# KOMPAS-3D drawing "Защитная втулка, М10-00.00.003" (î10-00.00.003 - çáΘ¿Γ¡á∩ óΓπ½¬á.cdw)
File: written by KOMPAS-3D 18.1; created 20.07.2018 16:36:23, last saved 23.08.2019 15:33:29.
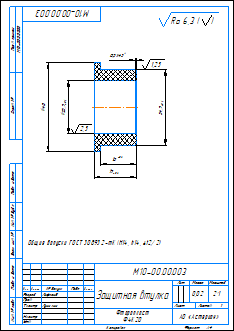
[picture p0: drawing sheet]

Sheet 1: A4, portrait

Document properties: Автор: Мирончук; Масса: 0.02; Параметр неуказанной шероховатости: Ra 6,3; Полное имя файла: М10-00.00.003 - Защитная втулка.m3d; Организация: Мирончук

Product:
- Part/product: Защитная втулка  | designation М10-00.00.003
    Масса: 0.0193569
    Раздел спецификации: Детали
    Форматы листов документа: A4
    source file: М10-00.00.003 - Защитная втулка.cdw

Title block, sheet 1: Наименование: Защитная втулка; designation: М10-00.00.003; Материал: Фторопласт / Ф4К20; Масса: 0,02; scale: 2:1; Количество листов документа: 1; organisation: АО «Астерион»; Форматы листов документа: A4; stored path: Z:\Магна\Магна Ins\Магна ins 10\М10-00.00.000\3Д\М10-00.00.003 - Защитная втулка.cdw; Разработал: Лифлянд; Т. контр.: Лучихин

Views: Вид 1, Местный разрез 1, Спереди, Проекционный вид 2
Referenced files in Z:\Магна\Магна Ins\Магна ins 10\М10-00.00.000\3Д\: М10-00.00.003 - Защитная втулка.m3d
Referenced files in D:\Magna\Магна Ins\Магна ins 10\М10-00.00.000\3Д\: М10-00.00.003 - Защитная втулка.m3d
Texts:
  Ra 6,3
  Ra 6,3 ( )
Dimensions and other numbers on the sheet: 23,9; 40; 34,9; 0,5; 16; 19; 1,25; 2,5; 2:1; 1; 0,02

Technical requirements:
  Общие допуски ГОСТ 30893.2-тК (H14, h14,  t2/2).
